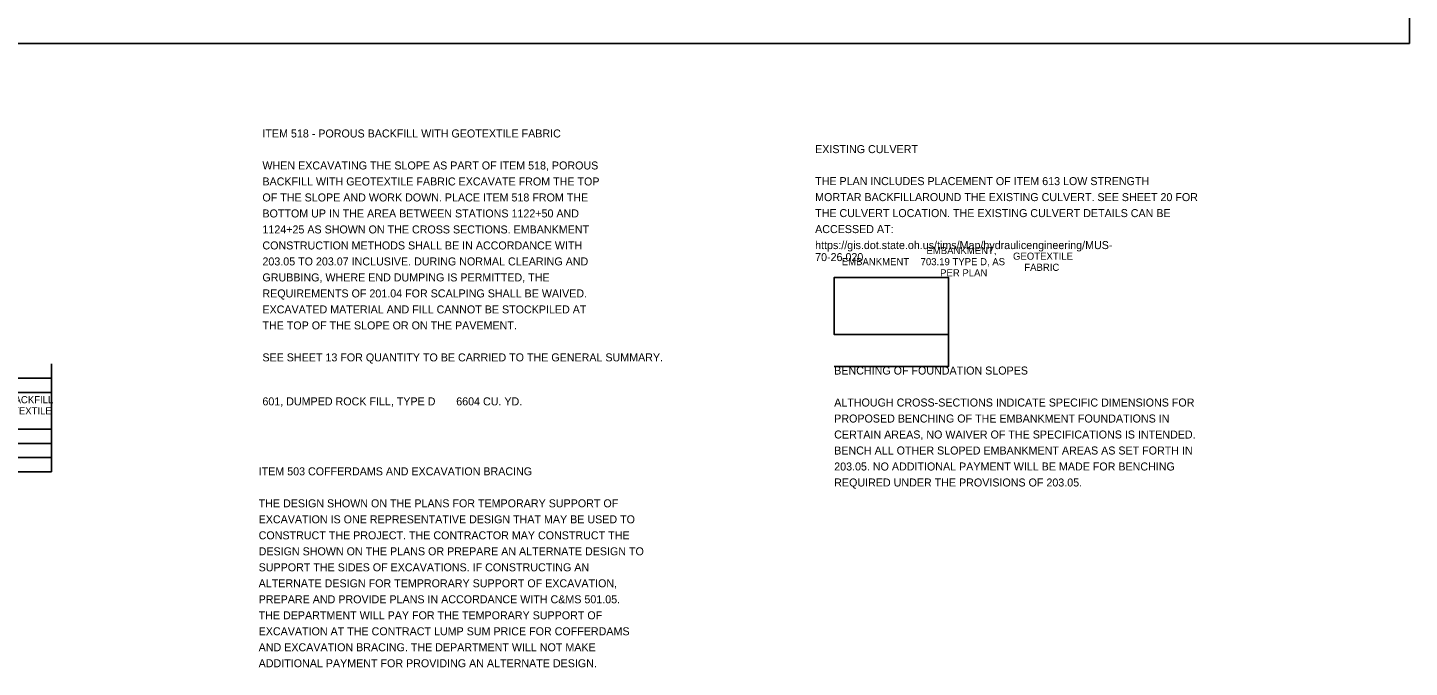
# Model space of a CAD drawing. Extents: x -8.9 to 34, y -10.9 to 22.
# Drawn here: x 9.82 to 34, y -10.92 to 0.28 of the extents above; entities that cross this region are included whole.
import ezdxf

# ---------------------------------------------------------------- set-up
doc = ezdxf.new("R2010")
doc.units = 0
for name, color, linetype in [('Default', 7, 'Continuous'), ('SH_Cut_Line', 7, 'Continuous'), ('SH_Data', 7, 'Continuous'), ('SH_Text', 7, 'Continuous')]:
    doc.layers.add(name, color=color, linetype=linetype)

msp = doc.modelspace()

# ---------------------------------------------------------------- linework, layer by layer
at = {"layer": 'Default'}
msp.add_lwpolyline([(25.935, -5.098), (25.935, -4.098), (23.935, -4.098), (23.935, -5.098)], close=True, dxfattribs=at)
msp.add_lwpolyline([(23.935, -5.098), (25.935, -5.098), (25.935, -5.658), (23.935, -5.658)], dxfattribs=at)
at = {"layer": 'SH_Cut_Line'}
msp.add_lwpolyline([(0, 0), (34, 0), (34, 22), (0, 22)], close=True, dxfattribs=at)
at = {"layer": 'SH_Data'}
for p, q in [((10.238, -7.503), (10.238, -5.613)), ((1.638, -5.863), (10.238, -5.863)), ((5.038, -6.113), (10.238, -6.113)), ((5.038, -6.753), (10.238, -6.753)), ((1.638, -7.003), (10.238, -7.003)), ((1.638, -7.253), (10.238, -7.253)), ((1.638, -7.503), (10.238, -7.503))]:
    msp.add_line(p, q, dxfattribs=at)

# ---------------------------------------------------------------- texts
for s, p in [('EMBANKMENT, ', (25.549, -3.69)), ('EMBANKMENT', (24.067, -3.885)), ('703.19 TYPE D, AS ', (25.447, -3.885)), ('GEOTEXTILE ', (27.064, -3.788)), ('FABRIC', (27.261, -3.983)), ('PER PLAN', (25.788, -4.08)), ('POROUS BACKFILL ', (8.709, -6.301)), ('WITH GEOTEXTILE ', (8.719, -6.496))]:
    msp.add_text(s, height=0.125, dxfattribs=at).set_placement(p)
at = {"layer": 'SH_Text'}
for s, p in [('ITEM 518 - POROUS BACKFILL WITH GEOTEXTILE FABRIC', (13.929, -1.648)), ('EXISTING CULVERT', (23.601, -1.922)), ('WHEN EXCAVATING THE SLOPE AS PART OF ITEM 518, POROUS ', (13.929, -2.208)), ('BACKFILL WITH GEOTEXTILE FABRIC EXCAVATE FROM THE TOP ', (13.929, -2.488)), ('THE PLAN INCLUDES PLACEMENT OF ITEM 613 LOW STRENGTH ', (23.601, -2.482)), ('OF THE SLOPE AND WORK DOWN. PLACE ITEM 518 FROM THE ', (13.929, -2.768)), ('MORTAR BACKFILLAROUND THE EXISTING CULVERT. SEE SHEET 20 FOR ', (23.601, -2.762)), ('THE CULVERT LOCATION. THE EXISTING CULVERT DETAILS CAN BE ', (23.601, -3.042)), ('BOTTOM UP IN THE AREA BETWEEN STATIONS 1122+50 AND ', (13.929, -3.048)), ('1124+25 AS SHOWN ON THE CROSS SECTIONS. EMBANKMENT ', (13.929, -3.328)), ('ACCESSED AT:', (23.601, -3.322)), ('CONSTRUCTION METHODS SHALL BE IN ACCORDANCE WITH ', (13.929, -3.608)), ('https://gis.dot.state.oh.us/tims/Map/hydraulicengineering/MUS-', (23.601, -3.602)), ('203.05 TO 203.07 INCLUSIVE. DURING NORMAL CLEARING AND ', (13.929, -3.888)), ('70-26.020', (23.601, -3.812)), ('GRUBBING, WHERE END DUMPING IS PERMITTED, THE ', (13.929, -4.168)), ('REQUIREMENTS OF 201.04 FOR SCALPING SHALL BE WAIVED. ', (13.929, -4.448)), ('EXCAVATED MATERIAL AND FILL CANNOT BE STOCKPILED AT ', (13.929, -4.728)), ('THE TOP OF THE SLOPE OR ON THE PAVEMENT.', (13.929, -5.008)), ('SEE SHEET 13 FOR QUANTITY TO BE CARRIED TO THE GENERAL SUMMARY.', (13.929, -5.568)), ('BENCHING OF FOUNDATION SLOPES', (23.935, -5.798)), ('601, DUMPED ROCK FILL, TYPE D       6604 CU. YD. ', (13.929, -6.338)), ('ALTHOUGH CROSS-SECTIONS INDICATE SPECIFIC DIMENSIONS FOR ', (23.935, -6.358)), ('PROPOSED BENCHING OF THE EMBANKMENT FOUNDATIONS IN ', (23.935, -6.638)), ('CERTAIN AREAS, NO WAIVER OF THE SPECIFICATIONS IS INTENDED. ', (23.935, -6.918)), ('BENCH ALL OTHER SLOPED EMBANKMENT AREAS AS SET FORTH IN ', (23.935, -7.198)), ('ITEM 503 COFFERDAMS AND EXCAVATION BRACING', (13.863, -7.563)), ('203.05. NO ADDITIONAL PAYMENT WILL BE MADE FOR BENCHING ', (23.935, -7.478)), ('REQUIRED UNDER THE PROVISIONS OF 203.05.', (23.935, -7.758)), ('THE DESIGN SHOWN ON THE PLANS FOR TEMPORARY SUPPORT OF ', (13.863, -8.123)), ('EXCAVATION IS ONE REPRESENTATIVE DESIGN THAT MAY BE USED TO ', (13.863, -8.403)), ('CONSTRUCT THE PROJECT. THE CONTRACTOR MAY CONSTRUCT THE ', (13.863, -8.683)), ('DESIGN SHOWN ON THE PLANS OR PREPARE AN ALTERNATE DESIGN TO ', (13.863, -8.963)), ('SUPPORT THE SIDES OF EXCAVATIONS. IF CONSTRUCTING AN ', (13.863, -9.243)), ('ALTERNATE DESIGN FOR TEMPRORARY SUPPORT OF EXCAVATION, ', (13.863, -9.523)), ('PREPARE AND PROVIDE PLANS IN ACCORDANCE WITH C&MS 501.05. ', (13.863, -9.803)), ('THE DEPARTMENT WILL PAY FOR THE TEMPORARY SUPPORT OF ', (13.863, -10.083)), ('EXCAVATION AT THE CONTRACT LUMP SUM PRICE FOR COFFERDAMS ', (13.863, -10.363)), ('AND EXCAVATION BRACING. THE DEPARTMENT WILL NOT MAKE ', (13.863, -10.643)), ('ADDITIONAL PAYMENT FOR PROVIDING AN ALTERNATE DESIGN.', (13.863, -10.923))]:
    msp.add_text(s, height=0.14, dxfattribs=at).set_placement(p)

doc.saveas('drawing.dxf')
